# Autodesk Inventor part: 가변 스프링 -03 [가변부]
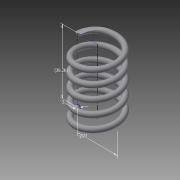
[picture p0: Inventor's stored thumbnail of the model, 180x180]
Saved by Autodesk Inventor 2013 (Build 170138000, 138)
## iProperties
Created: 2014-12
Part Number: 가변 스프링 -03 [가변부]
Material: Generic
Document SubType Name: Modeling
Designer: Administrator
Density: 1 g/cm^3
Mass: 2.40348 g
Surface Area: 32.5169 cm^2
Volume: 2.40348 cm^3
Author: Administrator
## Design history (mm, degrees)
sketch "Sketch1"
  geometry: L1 (0, 0)-(11, 0); L2 (11, 0)-(11, 36.261); L3 (11, 36.261)-(0, 36.261); L4 (0, 36.261)-(0, 0); C1 r 1.5 at (11, 0)
  constraints: 8 end point, 2 parallel, 1 centre point, 1 coincident, 1 horizontal, 1 perpendicular
  dimensions: "d0" = 3 diameter of C1; "d1" = 22 diameter of L2 L4; "d2" = 36.2612 distance between parallel lines of L1 L3 (derived)
coil "Coil1" pitch "d3" = 10; turns "d5" = 5; dims "d4" = 36.2612 (= d2), "d6" = 0, angle "d7" = 90 deg, angle "d8" = 90 deg, "d9" = 0, "d10" = 0
sketch "Sketch2"
  geometry: L1 (-12.5, 0)-(-9.5, 0) reference; 1 further point
  constraints: 1 horizontal alignment
extrude "Extrusion1" cut sketch "Sketch2" stored distance "d11" = 10; taper "d12" = 0 deg
workplane "Work Plane2"
sketch "Sketch3"
  geometry: L1 (1.5, 0)-(-1.5, 0) reference; 1 further point
  constraints: 1 horizontal alignment
extrude "Extrusion2" cut sketch "Sketch3" stored distance "d14" = 10; taper "d15" = 0 deg
body "Solid1"
node "Project Cut Edges1"
node "Project Cut Edges2"
other parameters: "d13" = 0
